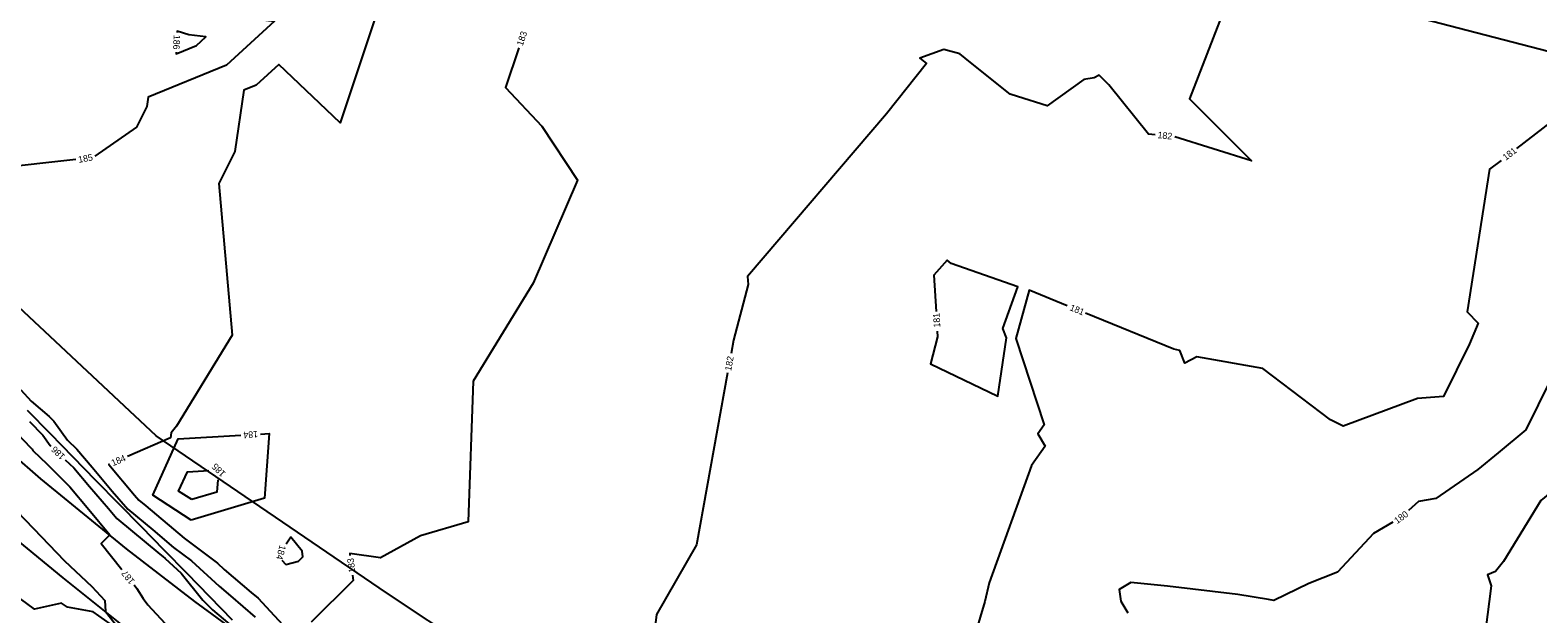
# Model space of a CAD drawing. Extents: x 2086416 to 2115205, y 575507 to 632762.
# Drawn here: x 2110459.9 to 2110919.3, y 581859.5 to 582037.5 of the extents above; entities that cross this region are included whole.
import ezdxf

# ---------------------------------------------------------------- set-up
doc = ezdxf.new("R2010")
doc.units = 0
for name, color, linetype in [('DTM Contours Major', 7, 'Continuous'), ('DTM Contours Major Text', 7, 'Continuous'), ('DTM Contours Minor', 7, 'Continuous'), ('DTM Contours Minor Text', 7, 'Continuous'), ('Exist Hydrographic FEMA Cross Section', 7, 'Continuous'), ('Exist Roads EOP', 7, 'Continuous'), ('Exist Vegetation Woods Line', 7, 'Continuous')]:
    doc.layers.add(name, color=color, linetype=linetype)

msp = doc.modelspace()

# ---------------------------------------------------------------- linework, layer by layer
at = {"layer": 'DTM Contours Major'}
for points in [[(2110505.52, 582043.98), (2110507.54, 582043.36), (2110534.29, 582040.27), (2110519.68, 582026.82), (2110495.82, 582017.05), (2110495.4, 582014.24), (2110492.28, 582007.94), (2110479.63, 581999.09)], [(2110473.79, 581998.1), (2110449.06, 581995.35), (2110449.38, 581967.78), (2110439.16, 581953.41), (2110445.67, 581945.45), (2110454.14, 581943.92), (2110456.52, 581933.16)], [(2110923.69, 581963.96), (2110933.17, 581954.23), (2110923.19, 581930.88), (2110915.68, 581915.67), (2110907.19, 581908.61), (2110901.05, 581903.53), (2110888.2, 581894.74), (2110882.96, 581893.82), (2110879.92, 581890.99)], [(2110457, 581927.88), (2110460.22, 581924.41), (2110465.69, 581919.7), (2110467.09, 581918.26), (2110471.2, 581912.48), (2110474.08, 581909.72), (2110478.74, 581904.23), (2110484.88, 581896.98), (2110489.67, 581891.41), (2110497.24, 581885.1), (2110503.54, 581879.8), (2110508.99, 581875.69), (2110517.48, 581867.91), (2110520.9, 581865), (2110528.46, 581858.48)], [(2110509.11, 581894.35), (2110505.12, 581896.95), (2110507.77, 581902.82), (2110514.29, 581903.21)], [(2110517.05, 581900.38), (2110516.78, 581896.66), (2110509.11, 581894.35)], [(2110875.11, 581887.46), (2110869.25, 581883.98), (2110858.27, 581872.27), (2110849.5, 581868.78), (2110838.87, 581863.56), (2110837.24, 581863.88), (2110827.93, 581865.43), (2110806.43, 581868), (2110795.23, 581869.03), (2110791.72, 581866.92), (2110792.22, 581863.37), (2110794.35, 581859.78)]]:
    msp.add_lwpolyline(points, dxfattribs=at)
at = {"layer": 'DTM Contours Minor'}
for points in [[(2110918.81, 582054.12), (2110874.3, 582057.26), (2110835.52, 582074.28), (2110813.19, 582016.55), (2110832.03, 581997.68), (2110808.69, 582005)], [(2110952.27, 582039.82), (2110870.6, 582045.58), (2110869.99, 582045.85), (2110869.64, 582044.94), (2110870.02, 582044.56), (2110870.37, 582044.22), (2110870.78, 582044.51), (2110943.97, 582025.54), (2110912.84, 582001.48)], [(2110565.03, 582041.29), (2110554.3, 582009.3), (2110535.63, 582027.04), (2110528.79, 582020.74), (2110525.03, 582019.2), (2110522.24, 582000.56), (2110517.36, 581990.74), (2110521.39, 581944.54), (2110504.51, 581916.72), (2110502.84, 581914.77), (2110502.62, 581913.15), (2110489.56, 581907.53)], [(2110510.57, 582032.89), (2110513.42, 582035.52), (2110508.21, 582036.12), (2110504.67, 582037.2), (2110504.65, 582036.8)], [(2110504.36, 582030.81), (2110504.33, 582030.34), (2110510.57, 582032.89)], [(2110608.77, 582032.18), (2110604.7, 582020.06), (2110615.79, 582008.2), (2110626.65, 581991.74), (2110613.13, 581960.39), (2110594.83, 581930.49), (2110593.3, 581887.59), (2110578.81, 581883.26), (2110566.59, 581876.57), (2110557.24, 581877.91), (2110557.32, 581877.29)], [(2110802.73, 582005.62), (2110800.66, 582005.79), (2110788.62, 582020.81), (2110785.6, 582023.76), (2110784.14, 582023), (2110780.99, 582022.49), (2110769.74, 582014.41), (2110760.76, 582017.27), (2110758.52, 582018.05), (2110746.4, 582027.71), (2110743.12, 582030.27), (2110738.33, 582031.6), (2110731.03, 582029.01), (2110733.04, 582027.31), (2110720.82, 582011.98), (2110678.47, 581962.39), (2110678.62, 581959.91), (2110674.17, 581942.97), (2110673.44, 581938.88)], [(2110908.09, 581997.81), (2110904.57, 581995.09), (2110897.77, 581951.62), (2110901.15, 581948.15), (2110898.46, 581941.86), (2110890.54, 581925.83), (2110882.6, 581925.22), (2110860.01, 581916.8), (2110856.12, 581918.65), (2110835.5, 581934.31), (2110815.41, 581937.86), (2110811.69, 581935.96), (2110810.26, 581939.8), (2110808.34, 581940.24), (2110781.42, 581951.24)], [(2110757.36, 581943.65), (2110756.27, 581946.57), (2110760.85, 581959.28), (2110740.53, 581966.4), (2110739.26, 581967.41), (2110735.29, 581962.76), (2110735.95, 581951.76)], [(2110775.86, 581953.5), (2110764.32, 581958.22), (2110760.24, 581943.47), (2110768.82, 581917.19), (2110766.89, 581914.46), (2110769.13, 581910.61), (2110764.97, 581904.78), (2110752.13, 581868.98), (2110750.83, 581863.28), (2110744.81, 581843.13), (2110744.47, 581839.04), (2110745.98, 581817.21), (2110759.85, 581811.8), (2110779.05, 581797.65)], [(2110736.31, 581945.77), (2110736.41, 581944.03), (2110734.24, 581935.76), (2110754.75, 581925.95), (2110757.36, 581943.65)], [(2110672.37, 581932.97), (2110662.96, 581880.6), (2110650.69, 581859.37), (2110649.72, 581851), (2110665.85, 581841.38), (2110668.3, 581839.83), (2110669.46, 581837.68), (2110668.83, 581836.73), (2110677.42, 581815.61), (2110643.22, 581798.5), (2110629.19, 581802.12), (2110627.72, 581804.48), (2110627.29, 581802.33), (2110628.54, 581801.21), (2110629.18, 581800.63), (2110629.48, 581800.67), (2110633.9, 581797.89)], [(2110447.54, 581923.19), (2110459.94, 581910.24), (2110460.45, 581909.72), (2110460.72, 581909.34), (2110465.06, 581905.18), (2110472.01, 581898.29), (2110477.76, 581891.3), (2110484.17, 581883.57), (2110481.54, 581880.96), (2110487.81, 581873.04)], [(2110459.63, 581918.22), (2110463.77, 581913.99), (2110465.96, 581910.91), (2110466.21, 581910.67)], [(2110508.92, 581888.12), (2110497.26, 581895.71), (2110505, 581912.85), (2110524.03, 581913.98)], [(2110530.02, 581914.34), (2110532.73, 581914.5), (2110531.28, 581894.84), (2110508.92, 581888.12)], [(2110470.54, 581906.52), (2110473.13, 581904.04), (2110477.96, 581898.35), (2110483.72, 581891.64), (2110486.31, 581888.63), (2110499.38, 581877.75), (2110500.28, 581876.99), (2110501.05, 581876.41), (2110505.9, 581871.97), (2110512.47, 581863.68), (2110515.46, 581860.72), (2110528.41, 581849.79)], [(2110484.05, 581905.15), (2110483.8, 581905.05), (2110491.71, 581895.71), (2110493.02, 581894.18), (2110495.1, 581892.45), (2110506.81, 581882.6), (2110516.92, 581874.96), (2110519.03, 581873.03), (2110527.21, 581866.07), (2110529.31, 581864.26), (2110539.23, 581853.65)], [(2110450.53, 581896.22), (2110460.85, 581885.58), (2110470.34, 581875.69), (2110478.68, 581867.9), (2110482.59, 581863.61), (2110482.79, 581860.24), (2110487.75, 581854.01), (2110479.08, 581860.14), (2110471.27, 581861.55), (2110469.42, 581862.78), (2110461.2, 581860.98), (2110453.09, 581866.98)], [(2110923.11, 581896.47), (2110920.2, 581894.07), (2110908.89, 581875.53), (2110906.44, 581872.43), (2110903.92, 581871.43), (2110905.1, 581868.04), (2110902.25, 581845.78), (2110903.28, 581828.56), (2110883.48, 581824.9), (2110902.68, 581808.48), (2110906.39, 581804.92), (2110921.27, 581803.56), (2110904.76, 581749.19), (2110904.98, 581746.94)], [(2110541.62, 581875.58), (2110542.97, 581876.91), (2110542.74, 581878.62), (2110539.26, 581882.92), (2110537.9, 581880.76)], [(2110536.58, 581875.87), (2110537.82, 581874.59), (2110541.62, 581875.58)], [(2110558.12, 581871.34), (2110558.34, 581869.72), (2110545.52, 581856.99)], [(2110491.53, 581868.34), (2110492.35, 581867.29), (2110494.27, 581864.16), (2110495.74, 581862.22), (2110508.87, 581848.12)]]:
    msp.add_lwpolyline(points, dxfattribs=at)
at = {"layer": 'Exist Hydrographic FEMA Cross Section'}
msp.add_lwpolyline([(2110521.57, 581857.56), (2110514.63, 581864.67), (2110507.69, 581871.78), (2110500.75, 581878.89), (2110493.81, 581886.01), (2110486.87, 581893.12), (2110479.93, 581900.23), (2110472.99, 581907.34), (2110466.06, 581914.46), (2110459.11, 581921.57)], dxfattribs=at)
at = {"layer": 'Exist Roads EOP'}
for points in [[(2110859.62, 581680.71), (2110839.18, 581687.57), (2110822.39, 581693.78), (2110804.41, 581700.49), (2110791.36, 581705.43), (2110777.14, 581711.28), (2110760, 581718.68), (2110741.24, 581726.89), (2110721.85, 581735.85), (2110702.22, 581745.1), (2110680.73, 581755.98), (2110662.27, 581765.85), (2110648.84, 581772.92), (2110632.22, 581782.31), (2110614.63, 581792.7), (2110596.64, 581803.91), (2110578.53, 581815.64), (2110567.83, 581822.57), (2110553.15, 581832.42), (2110531.54, 581847.48), (2110510.05, 581863.33), (2110489.25, 581879.31), (2110463.15, 581900.73), (2110445.32, 581916.19)], [(2110454.4, 581883.19), (2110469.83, 581870.54), (2110488.57, 581855.49), (2110506.88, 581841.42), (2110523.82, 581828.96), (2110539, 581818.5), (2110552.64, 581809.38), (2110568.55, 581798.72), (2110587.98, 581786.4), (2110607.77, 581774.2), (2110633.24, 581759.62), (2110661.71, 581744.29), (2110681.63, 581733.96), (2110708.85, 581721.01), (2110734.15, 581708.98), (2110768.01, 581694.36), (2110797.99, 581682.47), (2110825.02, 581672.22), (2110850.72, 581663.8), (2110872.12, 581657.17), (2110892.09, 581651.25), (2110910.76, 581646.06), (2110929.15, 581641.61)]]:
    msp.add_lwpolyline(points, dxfattribs=at)
at = {"layer": 'Exist Vegetation Woods Line'}
msp.add_lwpolyline([(2111059.79, 581657.65), (2110968.73, 581672.25), (2110864.06, 581705.25), (2110784.73, 581740.8), (2110702.3, 581784.67), (2110632.54, 581823.34), (2110568.48, 581865.95), (2110498.27, 581913.79), (2110441.66, 581966.78), (2110387.94, 582016.39), (2110334.43, 582063.69), (2110284.48, 582120.87)], dxfattribs=at)

# ---------------------------------------------------------------- texts
at = {"layer": 'DTM Contours Major Text'}
for s, rotation, p in [('185', 9.6503, (2110474.7, 581997.06)), ('185', 134.2774, (2110519.58, 581902.44)), ('180', 36.2769, (2110876.44, 581886.85))]:
    msp.add_text(s, height=2, rotation=rotation, dxfattribs=at).set_placement(p)
at = {"layer": 'DTM Contours Minor Text'}
for s, rotation, p in [('186', 267.137, (2110503.62, 582036.13)), ('183', 71.462, (2110609.95, 582032.55)), ('182', 354.0432, (2110803.35, 582004.61)), ('181', 37.701, (2110909.55, 581997.67)), ('181', 337.7896, (2110776.47, 581952.18)), ('181', 93.4252, (2110737.24, 581946.89)), ('182', 79.8136, (2110673.49, 581933.51)), ('184', 183.4133, (2110529.24, 581915.29)), ('186', 136.2363, (2110470.71, 581907.74)), ('184', 23.2893, (2110485.11, 581904.52)), ('184', 254.8708, (2110535.94, 581880.67)), ('183', 97.6385, (2110559.01, 581872.19)), ('187', 128.3449, (2110491.86, 581869.53))]:
    msp.add_text(s, height=2, rotation=rotation, dxfattribs=at).set_placement(p)

doc.saveas('drawing.dxf')
